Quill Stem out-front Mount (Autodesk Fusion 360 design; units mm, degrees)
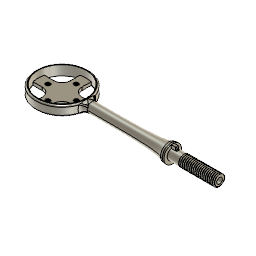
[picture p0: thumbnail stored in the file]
parameter "outer_diameter" = 33
parameter "big_rim_slot_gap" = 11.5
parameter "small_rim_width" = 1.75
parameter "big_rim_width" = 4
parameter "big_rim_height" = 1.4
parameter "total_height" = 7
parameter "distance_between_screw_holes" = 15
parameter "screw_hole_diameter" = 3
parameter "top_of_plate_to_top_of_rim" = 3.3
parameter "plate_thickness" = 3.7 (= "total_height - top_of_plate_to_top_of_rim")
parameter "start_of_locking_pin_from_centre" = 6
parameter "locking_pin_length" = 6
parameter "locking_pin_max_depth" = 1.2
parameter "locking_pin_width" = 2.4
parameter "pin_plate_width" = 10
parameter "pin_plate_cutout_width" = 1
parameter "screw_hole_distance_from_centre" = 8.75 (= "17.5 mm / 2")
parameter "pin_plate_fixed_slit_length" = 5
sketch "Sketch14" plane through (0, 0, 0) normal (0, 0, 1) x axis (1, 0, 0)
  circle C1 centre (0, 0) radius 17
  circle C2 centre (0, 0) radius 18.5
  point P1 (0, 0)
  point P2 (0, 0)
  coincident P1 P2
  dimension "d101" diameter C1 = 34
  dimension "d102" = 1.5
extrude "Extrude14" new body sketch "Sketch14" along normal blind 7
work_plane "WorkPlane2" AlongDistance 16
sketch "Sketch6" plane through (16, 0, 0) normal (1, 0, 0) x axis (0, 1, 0)
  line L1 (0, 7) -> (0, 0)
  circle C1 centre (0, 3.5) radius 3.5
  point P1 (0, 0)
  point P2 (0, 0)
  point P4 (0, 3.5)
  coincident P1 P2
  vertical L1
  midpoint L1 P4
  coincident P1 C1
extrude "Extrude7" add sketch "Sketch6" along normal blind 60
extrude "Extrude9" cut of existing geometry blind -55
work_plane "WorkPlane4" AlongDistance 8
extrude "Extrude10" add blind 25
loft "Loft2" Start Weight 2.4
extrude "Extrude11" add of existing geometry blind 10
sketch "Sketch13" plane through (76, 0, 0) normal (1, 0, 0) x axis (0, 1, 0)
  line L1 (1, 9.5) -> (-1, 9.5)
  line L2 (1, 5.5) -> (1, 9.5)
  line L3 (-1, 5.5) -> (-1, 9.5)
  line L4 (1, 5.5) -> (-1, 5.5)
  circle C1 centre (0, 3.5) radius 6.25
  circle C2 centre (0, 3.5) radius 3
  point P4 (1, 9.5)
  point P5 (1, 5.5)
  horizontal L1
  perpendicular L1 L2
  perpendicular L1 L3
  dimension "d92" distance P4 P5 = 4
thread "Thread2" ThreadOffset 0 ThreadLength 25
extrude "Extrude13" add of existing geometry blind 2
extrude "Extrude12" add sketch "Sketch13" profile of C2 L1 L2 L3 along normal blind 5.5
fillet "Fillet4" radius 0.5
sketch "Sketch15" plane through (0, 0, 7) normal (0, 0, 1) x axis (-1, 0, 0)
  circle C1 centre (0, 0) radius 18.5
  circle C2 centre (0, 0) radius 17
  point P1 (0, 0)
  point P3 (0, 0)
  coincident P1 P3
  dimension "d105" diameter C2 = 34
extrude "Extrude15" cut sketch "Sketch15" profile of C2 against normal blind 4.75
sketch "Sketch16" plane through (0, 0, 2.25) normal (0, 0, 1) x axis (-1, 0, 0)
  line L1 (-10, 0) -> (-17, 0)
  line L2 (10, 0) -> (17, 0)
  circle C1 centre (0, 0) radius 17
  point P3 (-17, 0)
  point P5 (17, 0)
  point P4 (-10, 0)
  point P6 (10, 0)
  coincident C1 P3
  horizontal L1
  coincident C1 P5
  horizontal L2
  dimension "d108" distance P3 P4 = 7
  dimension "d109" distance P5 P6 = 7
sketch "Sketch17" plane through (0, 0, 2.25) normal (0, 0, 1) x axis (-1, 0, 0)
  line L1 (-16.5227, -4) -> (-10, -4)
  line L2 (-16.5227, 4) -> (-10.0009, 4)
  line L3 (16.5227, 4) -> (10, 4)
  line L4 (16.5227, -4) -> (10, -4)
  line L5 (-10, -3) -> (10, -3)
  line L6 (10, 3) -> (-10, 3)
  line L7 (0, -10) -> (0, -17)
  line L8 (0, 10) -> (0, 17)
  line L9 (4, 16.5227) -> (4, 10)
  line L10 (-4, 16.5227) -> (-4, 10)
  line L11 (4.0009, -16.5225) -> (4, -9.9995)
  line L12 (-4.0022, -16.5222) -> (-4, -9.9987)
  circle C1 centre (0, 0) radius 17
  circle C2 centre (10, 0) radius 4
  circle C3 centre (-10.0009, 0) radius 4
  circle C4 centre (0, 10) radius 4
  circle C5 centre (0, -10) radius 4
  arc A1 centre (9.9987, -9.9987) radius 5.9987 clockwise from (4, -9.9995) to (10, -4)
  arc A2 centre (-9.9987, -9.9987) radius 5.9987 clockwise from (-10, -4) to (-4, -9.9987)
  arc A3 centre (-10, 10) radius 6 clockwise from (-4, 10) to (-10.0009, 4)
  arc A4 centre (10, 10) radius 6 clockwise from (10, 4) to (4, 10)
  point P5 (-10, -4)
  point P6 (-16.5227, -4)
  point P7 (-10.0009, 4)
  point P8 (-16.5227, 4)
  point P9 (10, 4)
  point P10 (16.5227, 4)
  point P11 (10, -4)
  point P12 (16.5227, -4)
  point P17 (0, -17)
  point P19 (0, 17)
  point P20 (0, 10)
  point P21 (0, 10)
  point P18 (0, -10)
  point P22 (0, -10)
  point P23 (4, -9.9995)
  point P25 (-4, -9.9987)
  point P27 (-4, 10)
  point P29 (4, 10)
  point P31 (4, 16.5227)
  point P32 (-4, 16.5227)
  point P33 (4.0009, -16.5225)
  point P34 (-4.0022, -16.5222)
  coincident C3 P5
  coincident C1 P6
  horizontal L1
  coincident C3 P7
  coincident C1 P8
  parallel L1 L2
  coincident C2 P9
  coincident C1 P10
  parallel L2 L3
  coincident C2 P11
  coincident C1 P12
  parallel L3 L4
  parallel L4 L5
  parallel L3 L6
  coincident C1 P17
  vertical L7
  coincident C1 P19
  vertical L8
  coincident P20 P21
  coincident P18 P22
  tangent C5 A1
  coincident C5 P23
  tangent C3 A2
  coincident C5 P25
  tangent C4 A3
  coincident C4 P27
  tangent L3 A4
  coincident C4 P29
  coincident C1 P31
  tangent C4 L9
  coincident C1 P32
  tangent C4 L10
  coincident C1 P33
  tangent C5 L11
  coincident C1 P34
  tangent C5 L12
  dimension "d119" diameter C3 = 8
  dimension "d120" distance P17 P18 = 7
  dimension "d121" distance P19 P20 = 7
  dimension "d122" diameter C5 = 8
hole "Hole2" HoleDepth 3.2 HoleDiameter 2.529 TipAngle 180
fillet "Fillet5" radius 1
fillet "Fillet6" radius 1
extrude "Extrude16" cut sketch "Sketch17" profile of C1 C2 C3 L1 L2 L3 L4 A1 A2 A3 A4 L9 L10 L11 L12 against normal blind 2.25
sketch "Sketch18" plane through (111, 0, 0) normal (1, 0, 0) x axis (0, 1, 0)
  curve K1 (1.7487, 7.0229) -> (1.8716, 0.8764)
  curve K2 (-1.8716, 0.8764) -> (-1.7487, 7.0229)
  arc A1 centre (0, 3.5) radius 3.933 clockwise from (-1.7487, 7.0229) to (1.7487, 7.0229)
  arc A2 centre (0, 3.5) radius 3.2227 clockwise from (1.8716, 0.8764) to (-1.8716, 0.8764)
  circle C1 centre (0, 3.5) radius 2
  concentric A1 C1
  dimension "d125" diameter C1 = 4
extrude "Extrude17" cut sketch "Sketch18" profile of C1 against normal blind 90
fillet "Fillet7" radius 2
combine "Combine4"
fillet "Fillet8" radius 4
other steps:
thread "Thread3" ThreadOffset 0 ThreadDepth 7.4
